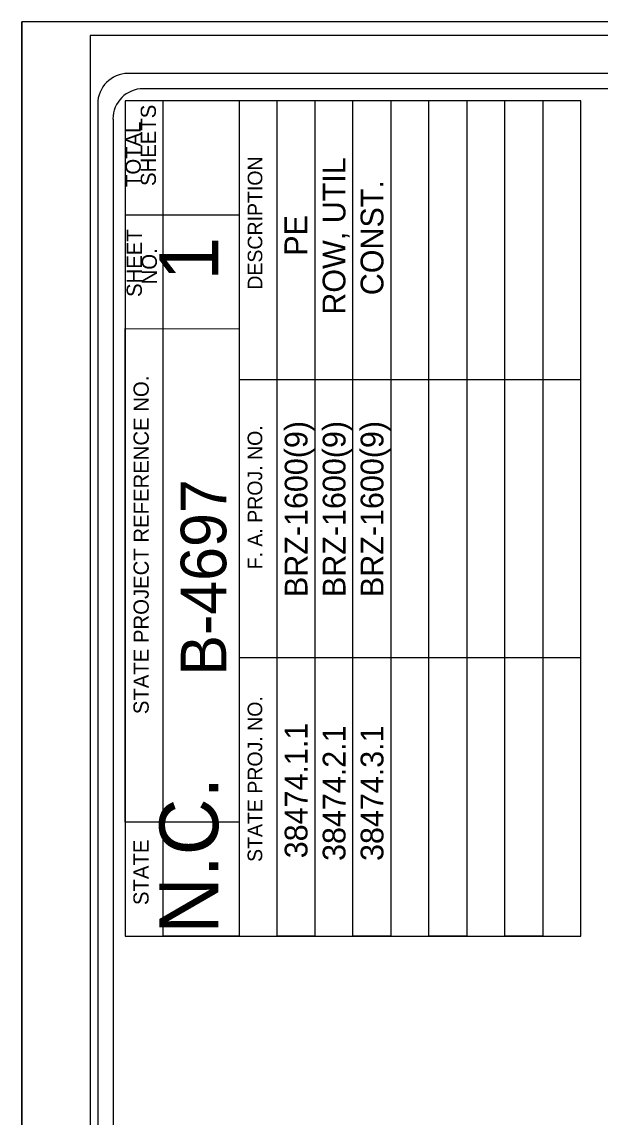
# Model space of a CAD drawing. Extents: x 2026893 to 2039781, y 729195 to 739590.
# Drawn here: x 2026893 to 2027559, y 738328 to 739590 of the extents above; entities that cross this region are included whole.
import ezdxf

# ---------------------------------------------------------------- set-up
doc = ezdxf.new("R2010")
doc.units = 0
for name, color, linetype in [('Sheet Cutting Line CELL', 7, 'Continuous'), ('Sheet Data Field CELL', 7, 'Continuous'), ('Sheet Plot Border Inside CELL', 7, 'Continuous'), ('Sheet Plot Border Outside CELL', 7, 'Continuous'), ('Sheet Title CELL', 7, 'Continuous')]:
    doc.layers.add(name, color=color, linetype=linetype)

msp = doc.modelspace()

# ---------------------------------------------------------------- linework, layer by layer
at = {"layer": 'Sheet Cutting Line CELL'}
msp.add_line((2026892.9, 733695.9), (2026892.9, 739589.9), dxfattribs=at)
at = {"layer": 'Sheet Plot Border Inside CELL'}
msp.add_lwpolyline([(2030664.3, 733741.4), (2030664.3, 739574.2), (2026971.4, 739574.2), (2026971.4, 733741.4)], close=True, dxfattribs=at)
at = {"layer": 'Sheet Plot Border Outside CELL'}
msp.add_lwpolyline([(2026892.9, 739589.9), (2026892.9, 733695.9), (2030742.8, 733695.9), (2030742.8, 739589.9)], close=True, dxfattribs=at)
at = {"layer": 'Sheet Title CELL'}
for points in [[(2030620.3, 739530.4), (2027015.4, 739530.4)], [(2029955.4, 739512.9), (2027032.8, 739512.9)], [(2027536.8, 738536.4), (2027536.8, 739498.9), (2027493.1, 739498.9), (2027493.1, 738536.4), (2027449.4, 738536.4), (2027449.4, 739498.9), (2027405.6, 739498.9), (2027405.6, 738536.5), (2027361.8, 738536.4), (2027361.8, 739498.9), (2027318.1, 739498.9), (2027318.1, 738536.4), (2027274.4, 738536.4), (2027274.3, 739498.9), (2027230.6, 739498.9), (2027230.6, 738536.4), (2027186.9, 738536.4), (2027186.9, 739498.9), (2027143.1, 739498.9), (2027143.1, 738536.4), (2027055.6, 738536.4), (2027055.6, 739498.9), (2027011.8, 739498.9), (2027011.9, 738536.4), (2027536.8, 738536.4), (2027536.9, 738857.2), (2027143.1, 738857.2), (2027143.1, 738667.7), (2027011.8, 738667.7), (2027011.9, 739236.5), (2027143.1, 739236.4), (2027143.1, 739178), (2027536.8, 739178), (2027536.8, 739498.9), (2027011.8, 739498.9), (2027011.8, 739367.7), (2027143.1, 739367.7)], [(2026980.4, 739495.5), (2026980.3, 734315.4)], [(2026997.9, 739477.9), (2026997.9, 734508)]]:
    msp.add_lwpolyline(points, dxfattribs=at)
for centre in [(2027015.2, 739495.5), (2027032.7, 739478)]:
    msp.add_arc(centre, 35, 90, 180, dxfattribs=at)

# ---------------------------------------------------------------- texts
at = {"layer": 'Sheet Data Field CELL'}
for s, height, p in [('ROW, UTIL', 26.25, (2027265.7, 739252.6)), ('CONST.', 26.25, (2027309.5, 739275)), ('PE', 26.25, (2027221.7, 739320.5)), ('BRZ-1600(9)', 26.25, (2027222, 738927.2)), ('BRZ-1600(9)', 26.25, (2027265.8, 738927.2)), ('BRZ-1600(9)', 26.25, (2027309.5, 738927.2)), ('B-4697', 52.5, (2027128.4, 738836.6)), ('38474.1.1', 26.25, (2027222, 738626.2)), ('38474.2.1', 26.25, (2027265.8, 738623.1)), ('38474.3.1', 26.25, (2027309.5, 738623.1))]:
    msp.add_text(s, height=height, rotation=90, dxfattribs=at).set_placement(p)
at = {"layer": 'Sheet Title CELL'}
for s, height, p in [('SHEETS', 17.5, (2027047.3, 739400.9)), ('TOTAL', 17.5, (2027029.8, 739399.7)), ('DESCRIPTION', 16.8, (2027169.9, 739281.4)), ('SHEET', 17.5, (2027031.1, 739273)), ('1', 67.7, (2027119.1, 739291.9)), ('NO.', 17.5, (2027048.4, 739287.5)), ('STATE PROJECT REFERENCE NO.', 17.499, (2027039, 738792.3)), ('F. A. PROJ. NO.', 16.8, (2027169.8, 738959.1)), ('STATE PROJ. NO.', 16.8, (2027169.8, 738622)), ('N.C.', 67.72, (2027119.1, 738539.1)), ('STATE', 17.5, (2027038.9, 738572.3))]:
    msp.add_text(s, height=height, rotation=90, dxfattribs=at).set_placement(p)

doc.saveas('drawing.dxf')
